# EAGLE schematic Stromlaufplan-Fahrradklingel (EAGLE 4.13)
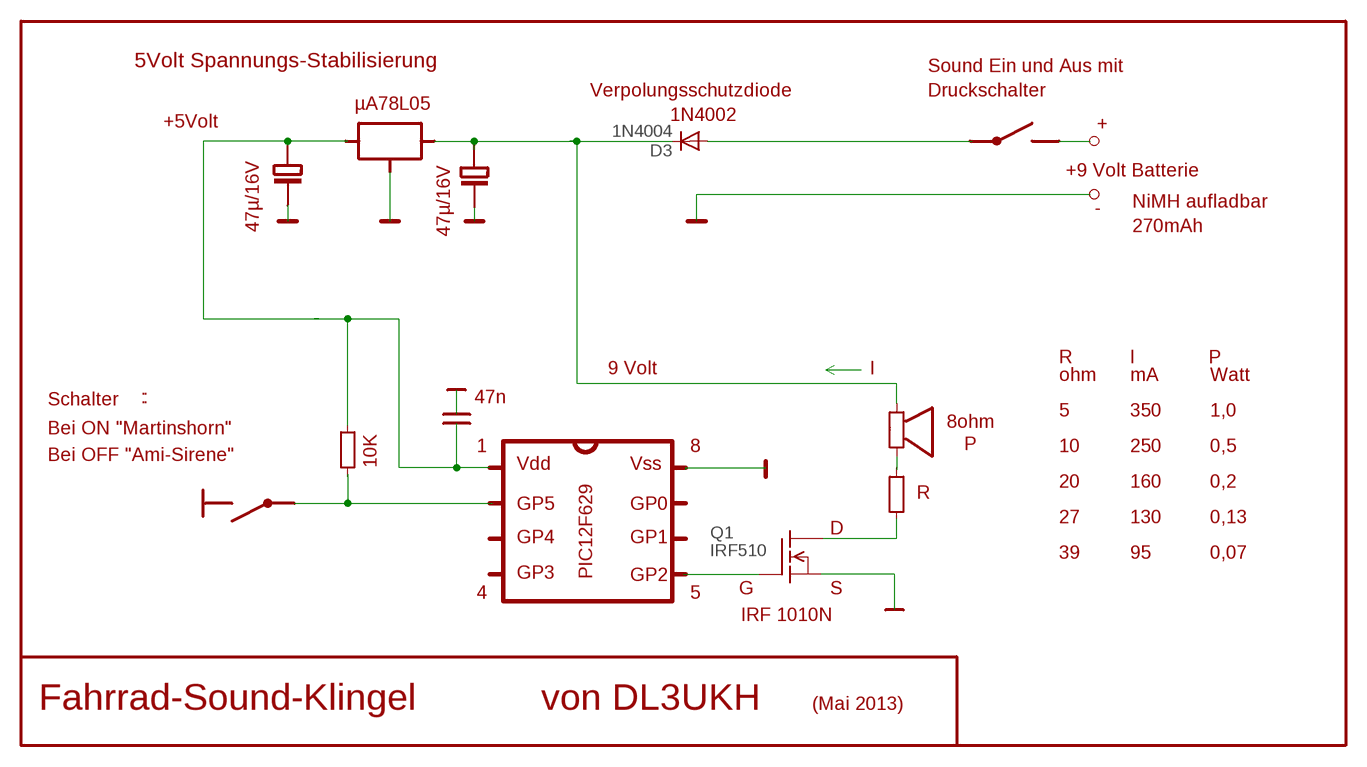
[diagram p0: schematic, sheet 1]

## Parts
D3  1N4004  [DO41-10]
Q1  IRF510  [TO220]

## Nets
N$2: D3.C
N$5: Q1.2(D)
N$13: Q1.3(S)
N$23: Q1.1(G)
N$47: D3.A

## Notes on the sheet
- 5Volt Spannungs-Stabilisierung | Sound Ein und Aus mit
- Verpolungsschutzdiode | Druckschalter
- µA78L05
- 1N4002
- +5Volt | +
- +9 Volt Batterie
- NiMH aufladbar
- -
- 47µ/16V | 47µ/16V | 270mAh
- P
- R | I
- 9 Volt | I
- ohm | mA | Watt
- Schalter | : | : | 47n
- 8ohm | 5 | 350 | 1,0
- Bei ON "Martinshorn" | P
- 1 | 8 | 10 | 250 | 0,5
- Bei OFF "Ami-Sirene"
- 10K | Vdd | Vss
- 20 | 160 | 0,2
- R
- GP5 | GP0
- 27 | 130 | 0,13
- D
- GP4 | GP1
- 39 | 95 | 0,07
- GP3 | PIC12F629 | GP2
- 4 | 5 | G | S
- IRF 1010N
- Fahrrad-Sound-Klingel | von DL3UKH | (Mai 2013)

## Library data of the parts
D3 = diode:1N4004: DIODE
Q1 = transistor-fet:IRF510: N-Channel Enhancement MOSFET (HEXFET); 100V; 5,6A; 0,54Ohm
